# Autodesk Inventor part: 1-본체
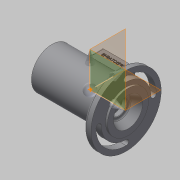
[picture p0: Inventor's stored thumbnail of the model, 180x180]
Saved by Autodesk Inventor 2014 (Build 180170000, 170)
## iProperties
Created: 2017-05
Part Number: 1-본체
Material: Generic
Document SubType Name: Modeling
Designer: Administrator
Density: 1 g/cm^3
Appearance: Default
Author: Administrator
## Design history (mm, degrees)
sketch "Sketch1"
  geometry: L1 (-56, 0)-(59, 0); L2 (-56, 0)-(-56, 31); L3 (59, 0)-(59, 31); L4 (59, 31)-(56, 31); L5 (56, 31)-(56, 53); L6 (56, 53)-(46, 53); L7 (46, 53)-(46, 31); L8 (46, 31)-(-56, 31); 1 further point
  constraints: 16 end point, 6 perpendicular, 1 horizontal, 1 parallel
  dimensions: "d2" = 115 distance of L1.start L1.end; "d9" = 3 distance between parallel lines of L3 L5; "d10" = 13 distance between parallel lines of L3 L7; "d11" = 22 distance between parallel lines of L4 L6; "d12" = 62 diameter of L4 L1; "d13" = 0 distance between parallel lines of L4 L8; "d17" = 31 distance of L1.start L2.end (derived); "d18" = 56 distance of point (0, 0) L1.start; "d19" = 59 distance of L1.end point (0, 0)
revolve "Revolution1" sketch "Sketch1" stored, may be unused: angle "d20" = 90 deg
workplane "Work Plane1"
sketch "Sketch2"
  geometry: L1 (25, -20)-(-25, -20); L2 (-25, -20)-(-25, 20); L3 (-25, 20)-(25, 20); L4 (25, 20)-(25, -20); L5 (25, -20)-(-25, 20); L6 (-25, -20)-(25, 20); 2 further points
  constraints: 12 end point, 2 midpoint, 2 parallel, 1 horizontal, 1 perpendicular
  dimensions: "d22" = 50 distance of L2.end L3.end; "d23" = 40 distance of L1.end L2.end; "d24" = 56 horizontal distance of point (0, 0) point (56, -31) (derived)
extrude "Extrusion1" join sketch "Sketch2" stored distance "d25" = 10; taper "d26" = 0 deg
sketch "Sketch3"
  geometry: L1 (-47, 24)-(-44, 24); L2 (-47, 24)-(-47, 0); L3 (-44, 24)-(-44, 20); L4 (-19, 17.438)-(-19, 26); L5 (-19, 26)-(19, 26); L6 (19, 26)-(19, 17.5); L7 (30, 16.5)-(30, 17.5); L8 (30, 17.5)-(19, 17.5); L9 (-30, 17.438)-(-19, 17.438); L10 (-35, 17.5)-(-35, 20); L11 (-35, 20)-(-44, 20); L12 (-30, 17.438)-(-30, 18.5); L13 (-30, 18.5)-(-31.75, 18.5); L14 (-31.75, 17.5)-(-35, 17.5); L15 (45, 12.5)-(45, 16); L16 (59, 0)-(59, 22); L17 (45, 16)-(59, 22); L18 (37.7, 10)-(37.7, 12.5); L19 (37.7, 12.5)-(45, 12.5); L20 (35, 10)-(35, 16.5); L21 (35, 16.5)-(30, 16.5); L22 (35, 10)-(37.7, 10); L23 (-47, 0)-(59, 0); L24 (-31.75, 18.5)-(-31.75, 17.5); L25 (-31.75, 0)-(-31.75, -0.062); 2 further points
  constraints: 50 end point, 12 parallel, 11 perpendicular, 1 horizontal, 1 point on line
  dimensions: "d96" = 48 diameter of L1.start L23; "d97" = 40 diameter of L3.end L23; "d98" = 35 diameter of L10.start L23; "d99" = 37 diameter of L13.end L23; "d100" = 52 diameter of L4.end L23; "d101" = 35 diameter of L6.end L23; "d102" = 33 diameter of L7.start L23; "d103" = 20 diameter of L20.start L23; "d104" = 25 diameter of L18.end L23; "d105" = 32 diameter of L15.end L23; "d106" = 44 diameter of L16.end L23; "d107" = 12 horizontal distance of L3.end point (-56, -31); "d108" = 3 distance of L1.start L1.end; "d111" = 60 horizontal distance of L7.start L9.start; "d112" = 5 distance of L20.end L7.start; "d113" = 14 horizontal distance of L15.end L16.start; "d116" = 23.99962 horizontal distance of L16.start L20.start; "d117" = 38 distance of L4.end L5.end; "d122" = 4.93828 distance between parallel lines of L19 L9; "d123" = 3.02005 distance from line of point (0, 0) L17; "d124" = 15.47011 distance from line of L25.end L17; "d125" = 21.3 distance between parallel lines of L18 L16; "d126" = 39.99962 distance between parallel lines of L6 L16; "d127" = 90.74962 distance between parallel lines of L24 L16; "d128" = 90.74962 distance between parallel lines of L25 L16; "d129" = 94 distance between parallel lines of L10 L16; "d130" = 103 distance between parallel lines of L3 L16
revolve "Revolution2" sketch "Sketch3" stored, may be unused: angle "d131" = 90 deg; dims "d24" = 56 (derived)
sketch "Sketch4"
  geometry: C1 r 31 at (0, 0) reference; 1 further point
  constraints: 1 coincident
hole "Hole1" sketch "Sketch4" at (0, 0) diameter "d132" = 40.376; stored, may be unused: countersink angle "d136" = 90 deg, drill point angle "d138" = 118 deg; dims "d133" = 9, "d134" = 4, "d135" = 2, "d137" = 9
sketch "Sketch5"
  geometry: L1 (-16, 11)-(16, 11); L2 (16, 11)-(16, -11); L3 (16, -11)-(-16, -11); L4 (-16, -11)-(-16, 11); L5 (-16, 11)-(16, -11); L6 (16, 11)-(-16, -11); 1 further point
  constraints: 12 end point, 2 midpoint, 2 parallel, 1 horizontal, 1 perpendicular
  dimensions: "d139" = 32 distance of L2.end L3.end; "d140" = 22 distance of L1.end L2.end
extrude "Extrusion2" cut sketch "Sketch5" distance "d141" = 30; taper "d142" = 0 deg
sketch "Sketch6"
  geometry: L1 (-20.5, 15.5)-(20.5, 15.5); L2 (20.5, 15.5)-(20.5, -15.5); L3 (20.5, -15.5)-(-20.5, -15.5); L4 (-20.5, -15.5)-(-20.5, 15.5); L5 (-20.5, 15.5)-(20.5, -15.5); L6 (20.5, 15.5)-(-20.5, -15.5); 5 further points
  constraints: 12 end point, 4 coincident, 2 midpoint, 2 parallel, 1 horizontal, 1 perpendicular
  dimensions: "d143" = 41 distance of L2.end L3.end; "d144" = 31 distance of L1.end L2.end
hole "Hole2" sketch "Sketch6" at (-20.5, 15.5), (-20.5, -15.5), (20.5, -15.5), (20.5, 15.5) diameter "d145" = 2.459; stored, may be unused: countersink angle "d149" = 90 deg, drill point angle "d151" = 118 deg; dims "d146" = 6, "d147" = 4, "d148" = 2, "d150" = 8
sketch "Sketch7"
  geometry: C1 r 53 at (0, 0); C2 r 53 at (0, 0) reference; A1 r 37.5 centre (0, 0) between (0, 37.5) and (-37.5, 0); A2 r 45.5 centre (0, 0) between (0, 45.5) and (-45.5, 0); A3 r 4 centre (0, 41.5) between (0, 37.5) and (0, 45.5); A4 r 4 centre (-41.5, 0) between (-45.5, 0) and (-37.5, 0); A5 r 4 centre (41.5, 0) between (45.5, 0) and (37.5, 0); A6 r 45.5 centre (0, 0) between (0, -45.5) and (45.5, 0); A7 r 37.5 centre (0, 0) between (0, -37.5) and (37.5, 0); A8 r 4 centre (0, -41.5) between (0, -37.5) and (0, -45.5); 1 further point
  constraints: 16 point on circle, 9 centre point, 4 tangent, 3 coincident, 1 concentric
  dimensions: "d152" = 106 diameter of C1; "d154" = 75 diameter of A1; "d155" = 91 diameter of A2; "d157" = 8 diameter of A4; "d158" = 4 radius of A3; "d165" = 4 radius of A5; "d166" = 45.5 radius of A6; "d167" = 37.5 radius of A7; "d168" = 4 radius of A8; "d169" = 64.34672 distance of A5.start A2.start; "d170" = 58.96185 distance of A5.start A7.start; "d171" = 83 distance of A5.start A1.end
extrude "Extrusion3" cut sketch "Sketch7" distance "d161" = 20; taper "d162" = 0 deg
extrude "Extrusion4" cut sketch "Sketch7" distance "d172" = 20; taper "d173" = 0 deg
fillet "Fillet1" dims "d181" = 3, "d182" = 0.3
chamfer "Chamfer2" distance "d183" = 0.7; stored, may be unused: second distance "d184" = 2, angle "d185" = 30 deg
chamfer "Chamfer3" distance "d186" = 1; stored, may be unused: second distance "d187" = 2, angle "d188" = 45 deg
chamfer "Chamfer4" distance "d189" = 1; stored, may be unused: second distance "d190" = 2, angle "d191" = 45 deg
sketch "Sketch8"
  geometry: L1 (-31, -75)-(-31, -13) reference; 3 further points
  constraints: 1 other
  dimensions: "d174" = 8 vertical distance of point (25, -8) point (50, 0); "d175" = 56 distance from line of point (25, -8) L1
emboss "Emboss1" sketch "Sketch8" dims "d2" = 115, "d9" = 3, "d10" = 13, "d11" = 22, "d12" = 62, "d13" = 0, "d17" = 31 (derived), "d18" = 56, "d19" = 59, "d176" = 0.5, "d177" = 0
fillet "Fillet2" dims "d192" = 3
fillet "Fillet3" dims "d193" = 3
chamfer "Chamfer5" distance "d194" = 1; stored, may be unused: second distance "d195" = 2, angle "d196" = 45 deg
body "Solid1"
other parameters: "d21" = 44
